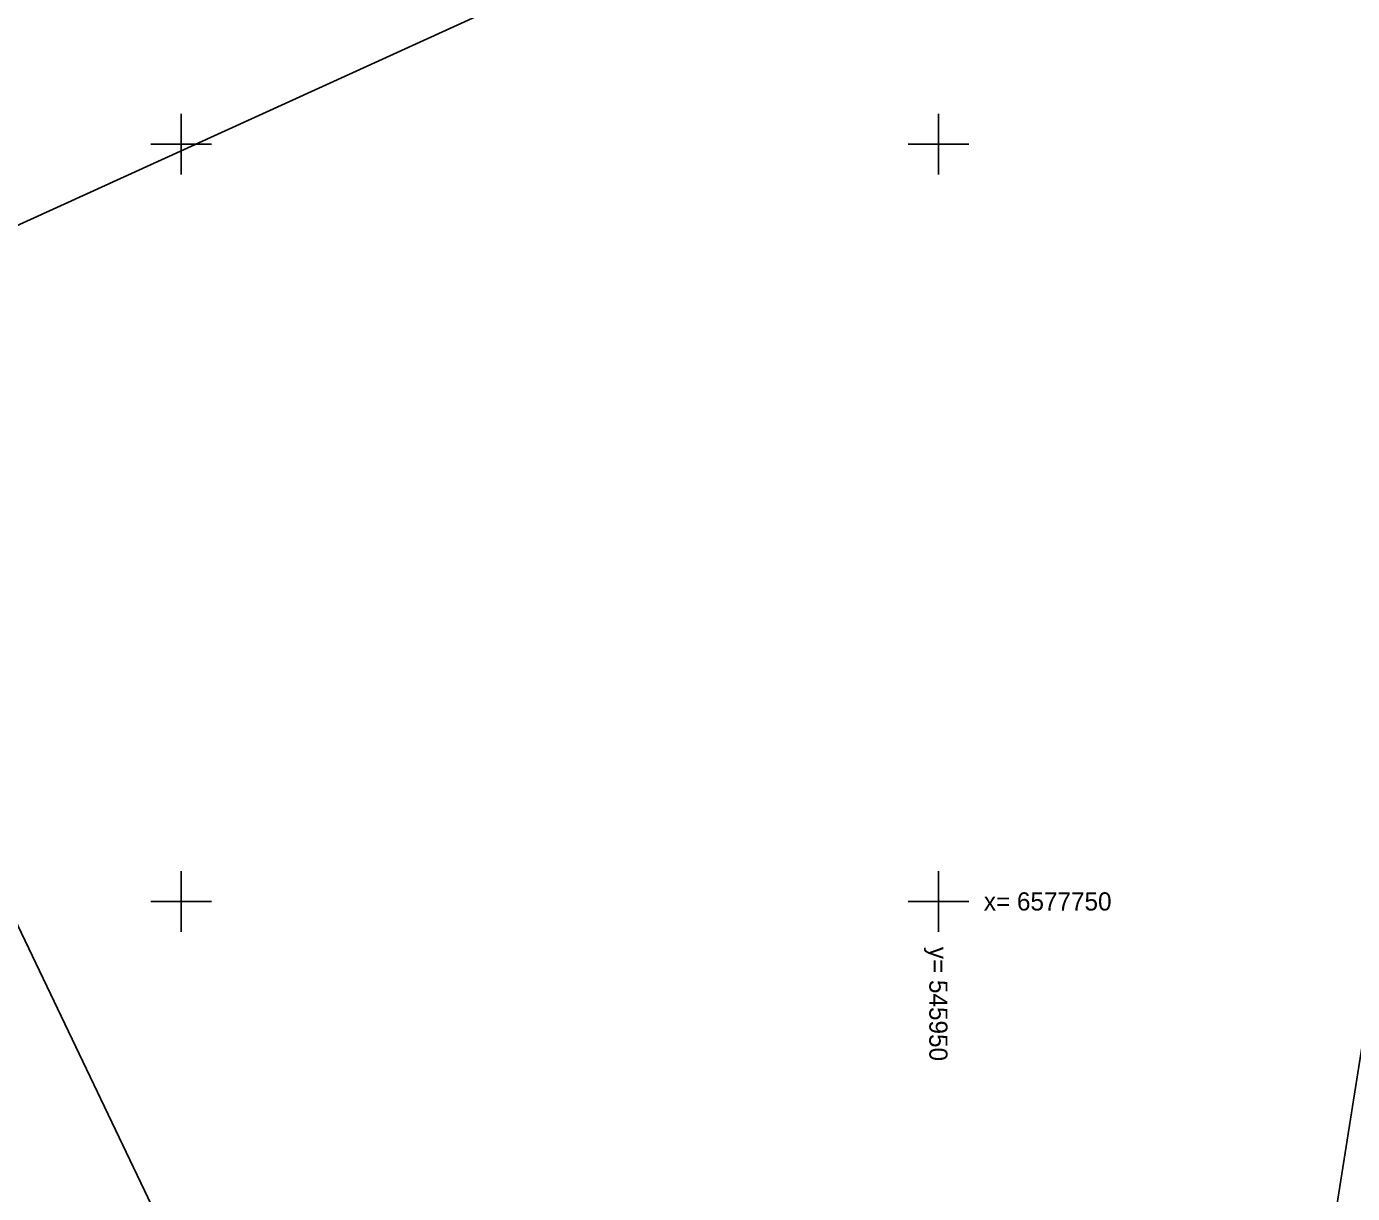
# Model space of a CAD drawing. Extents: x 543497 to 552146, y 6567125 to 6579845.
# Drawn here: x 545889.8 to 545977.3, y 6577730.7 to 6577807.8 of the extents above; entities that cross this region are included whole.
import ezdxf

# ---------------------------------------------------------------- set-up
doc = ezdxf.new("R2010")
doc.units = 0
doc.layers.add('xref_Kangru tee 1_geodeesia$0$PIIR', color=7, linetype='Continuous')
doc.layers.add('xref_Kangru tee 1_geodeesia$0$vork', color=7, linetype='Continuous')

# ---------------------------------------------------------------- blocks, each defined once
blk = doc.blocks.new('xref_Kangru tee 1_geodeesia$0$VKORIS')
for p, q in [((0, 4), (0, -4)), ((-4, 0), (4, 0))]:
    blk.add_line(p, q)

msp = doc.modelspace()

# ---------------------------------------------------------------- linework, layer by layer
at = {"layer": 'xref_Kangru tee 1_geodeesia$0$PIIR'}
for points in [[(545872.69, 6577782.96), (545871.05, 6577786.39), (545874.7, 6577788.05), (545922.19, 6577809.68), (545973.61, 6577832.94), (545956.36, 6577869.23), (545939.5, 6577905.43), (546028.71, 6577946.4), (546081.11, 6577806.12), (545983.53, 6577775.51), (545969.55, 6577687.28), (545921.7, 6577673.29), (545918.84, 6577672.45), (545911.34, 6577697.47), (545909.71, 6577702.91), (545909.43, 6577705.29), (545905.92, 6577713.46), (545874.41, 6577779.36), (545872.69, 6577782.96)], [(545858.78, 6577811.93), (545853.73, 6577822.44), (545857.98, 6577824.38), (545905.15, 6577845.89), (545922.19, 6577809.68), (545874.7, 6577788.05), (545871.05, 6577786.39), (545870.6, 6577787.32), (545858.78, 6577811.93)], [(545858.78, 6577811.93), (545870.6, 6577787.32), (545871.05, 6577786.39), (545872.69, 6577782.96), (545874.41, 6577779.36), (545905.92, 6577713.46), (545909.43, 6577705.29), (545909.71, 6577702.91), (545911.34, 6577697.47), (545918.84, 6577672.45), (545925.88, 6577650.4)], [(545983.53, 6577775.51), (546081.11, 6577806.12), (546096.86, 6577764.18), (546079.41, 6577756.98), (546054.12, 6577754.83), (546055.48, 6577740.79), (546080.65, 6577742.83), (546099.69, 6577747.34), (546110.26, 6577728.46), (545969.55, 6577687.28), (545983.53, 6577775.51)]]:
    msp.add_lwpolyline(points, dxfattribs=at)

# ---------------------------------------------------------------- block references
at = {"layer": 'xref_Kangru tee 1_geodeesia$0$vork', "xscale": 0.5, "yscale": 0.5}
for p in [(545900, 6577800), (545950, 6577800), (545900, 6577750), (545950, 6577750)]:
    msp.add_blockref('xref_Kangru tee 1_geodeesia$0$VKORIS', p, dxfattribs=at)

# ---------------------------------------------------------------- texts
at = {"layer": 'xref_Kangru tee 1_geodeesia$0$vork'}
msp.add_text('x= 6577750', height=1.2, dxfattribs=at).set_placement((545953, 6577749.4))
msp.add_text('y= 545950', height=1.2, rotation=270, dxfattribs=at).set_placement((545949.4, 6577747))

doc.saveas('drawing.dxf')
